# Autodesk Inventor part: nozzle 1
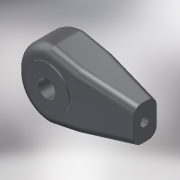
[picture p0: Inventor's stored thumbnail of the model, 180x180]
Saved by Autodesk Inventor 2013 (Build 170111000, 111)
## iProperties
Shininess: 69.0
Length Units: 11269
Angle Units: 11279
Time Units: 11290
Mass Units: 11283
Length Display Precision: 3
Angle Display Precision: 2
Created: 2002-03
Part Number: nozzle 1
Material: UHMW, Black
Document SubType Name: Modeling
Designer: =<Author>
Density: 0.94 g/cm^3
Description: =<Part Number>
Density: 0.94
Volumn: 7.4694824136698434
Area: 25.269763052910612
PropertySet Name: Model Information
Control State: 0
Master: False
Checked Out: True
Last Check In Date: 2008-10-15
Checked Out Date: 2008-10-15
Author: LAlexey
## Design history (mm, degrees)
sketch "Sketch1"
  geometry: L1 (-25.463, 26.268)-(-5.463, 26.268); L2 (-5.463, 26.268)-(12.079, 23.768); L3 (12.079, 23.768)-(12.079, 15.768); L4 (12.079, 15.768)-(-5.463, 13.268); L5 (-5.463, 13.268)-(-25.463, 13.268); L6 (-25.463, 13.268)-(-25.463, 26.268)
  constraints: 12 end point, 2 equal length, 2 parallel, 1 horizontal, 1 perpendicular
  dimensions: "d0" = 13 distance between parallel lines of L5 L1; "d1" = 8 distance of L2.end L3.end; "d2" = 20 distance of L1.start L1.end
extrude "Extrusion1" new body sketch "Sketch1" distance "d3" = 23; taper "d4" = 0 deg
fillet "Fillet1" dims "d5" = 11
sketch "Sketch2"
  geometry: L1 (-9, 23)-(17.542, 17.5); L2 (-9, 0)-(17.542, 5.5); L3 (17.542, 23)-(17.542, 0) reference; L4 (17.542, 17.5)-(17.542, 5.5); L5 (-9, 23)-(17.542, 23); L6 (0, 23)-(17.542, 23) reference; L7 (-9, 0)-(17.542, 0); L8 (17.542, 23)-(17.542, 0); A1 r 11 centre (-9, 11) between (-20, 11) and (-9, 0) reference; A2 r 11 centre (-9, 12) between (-9, 23) and (-20, 12) reference
  constraints: 12 end point, 2 collinear, 2 point on line, 2 tangent, 1 equal length, 1 parallel
  dimensions: "d6" = 12 distance of L2.end L1.end
extrude "Extrusion2" cut sketch "Sketch2" distance "d7" = 23; taper "d8" = 0 deg
fillet "Fillet2" dims "d9" = 3
sketch "Sketch3"
  geometry: C1 r 7.5 at (-9, 6.571); A1 r 8 centre (-9, 7.071) between (-9.283, 15.066) and (-17, 7.071) reference; A2 r 8 centre (-9, 6.071) between (-17, 6.071) and (-9.283, -1.924) reference
  constraints: 1 centre point
  dimensions: "d10" = 0.5 distance of A1.centre C1.centre; "d11" = 0.5 distance of A2.centre C1.centre; "d12" = 15 diameter of C1
extrude "Extrusion3" join sketch "Sketch3" distance "d13" = 0.5; taper "d14" = 0 deg
sketch "Sketch4"
  geometry: C1 r 7.5 at (-9, 6.571) reference
extrude "Extrusion4" join sketch "Sketch4" distance "d15" = 0.5; taper "d16" = 0 deg
sketch "Sketch5"
  geometry: C1 r 7.5 at (0, 0) reference; C2 r 3 at (0, 0)
  constraints: 1 centre point, 1 coincident
  dimensions: "d17" = 6 diameter of C2
extrude "Extrusion5" cut sketch "Sketch5" distance "d18" = 500; taper "d19" = 0 deg
workaxis "Work Axis1"
sketch "Sketch6"
  geometry: L1 (-6, 10.856)-(-6, -8.744) reference; L2 (-13.5, 8.056)-(1.5, 8.056) reference; L3 (1.5, -5.944)-(-13.5, -5.944) reference; C1 r 1.5 at (-6, 1.056)
  constraints: 1 centre point
  dimensions: "d20" = 3 diameter of C1; "d21" = 0 distance from line of L1 C1.centre; "d22" = 7 distance from line of L2 C1.centre; "d23" = 7 distance from line of C1.centre L3 (derived)
extrude "Extrusion6" cut sketch "Sketch6" distance "d24" = 5; taper "d25" = 0 deg
body "Solid1"
